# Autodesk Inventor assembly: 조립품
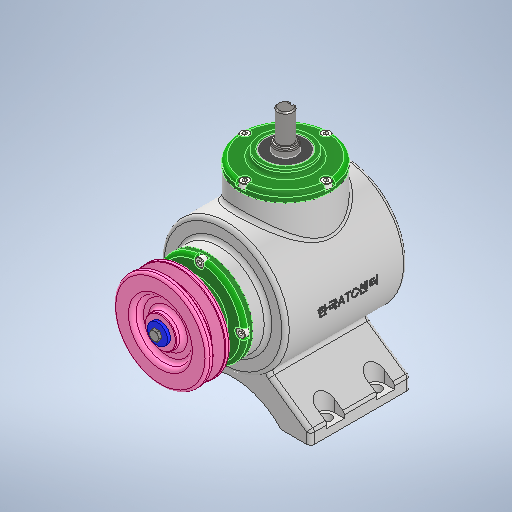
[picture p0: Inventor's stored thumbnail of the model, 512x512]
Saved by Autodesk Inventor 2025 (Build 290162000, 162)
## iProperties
Created: 2024-07
Part Number: 조립품
Document SubType Name: Assembly
Designer: 학생
Author: 학생
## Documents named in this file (15)
- C:\Users\학생\Desktop\740709V1003\조립품.iam
- C:\Users\학생\Desktop\석유림\0712 도면\01 20240518\공용부품_20240518_2\Ű 4 x 4 x 14\Ű 4 x 4 x 14.ipt
- C:\Users\학생\Desktop\석유림\0712 도면\01 20240518\공용부품_20240518_2\Ű 5 x 5 x 14\Ű 5 x 5 x 14.ipt
- C:\Users\학생\Desktop\석유림\0712 도면\01 20240518\공용부품_20240518_2\V-벨트풀리\V-벨트풀리.ipt
- C:\Users\학생\Desktop\석유림\0712 도면\01 20240518\공용부품_20240518_2\메인 베벨기어\메인 베벨기어.ipt
- C:\Users\학생\Desktop\석유림\0712 도면\01 20240518\공용부품_20240518_2\메인 축\메인 축.ipt
- C:\Users\학생\Desktop\석유림\0712 도면\01 20240518\공용부품_20240518_2\베어링 6203\베어링 6203.ipt
- C:\Users\학생\Desktop\석유림\0712 도면\01 20240518\공용부품_20240518_2\볼트 M4 x 10\볼트 M4 x 10.ipt
- C:\Users\학생\Desktop\석유림\0712 도면\01 20240518\공용부품_20240518_2\서브 베벨기어\서브 베벨기어.ipt
- C:\Users\학생\Desktop\석유림\0712 도면\01 20240518\공용부품_20240518_2\서브 축\서브 축.ipt
- C:\Users\학생\Desktop\석유림\0712 도면\01 20240518\공용부품_20240518_2\오일실 17 x 32 x 8\오일실 17 x 32 x 8.ipt
- C:\Users\학생\Desktop\석유림\0712 도면\01 20240518\공용부품_20240518_2\와셔 4 x 16\와셔 4 x 16.ipt
- C:\Users\학생\Desktop\석유림\0712 도면\01 20240518\공용부품_20240518_2\육각볼트 M4 x 8\육각볼트 M4 x 8.ipt
- C:\Users\학생\Desktop\석유림\0712 도면\01 20240518\공용부품_20240518_2\커버\커버.ipt
- C:\Users\학생\Desktop\740709V1003\본체.ipt
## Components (4 placed, 3 different names)
1. Ű 4 x 4 x 14:1
2. Ű 5 x 5 x 14:1
3. V-벨트풀리:1
4. Ű 4 x 4 x 14:2 — 각도:6, 각도:7
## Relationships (2: Angle 2)
- 각도:6 [Angle]: Ű 4 x 4 x 14:2
- 각도:7 [Angle]: Ű 4 x 4 x 14:2
